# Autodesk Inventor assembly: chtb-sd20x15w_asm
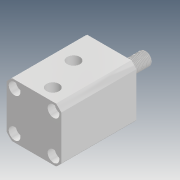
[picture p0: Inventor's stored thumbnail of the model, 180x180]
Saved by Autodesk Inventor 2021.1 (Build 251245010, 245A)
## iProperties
Company: Microsoft
Created: 2018-05
Part Number: chtb-sd20x15w_asm
Description: STEP AP214
Document SubType Name: Assembly
Designer: user
Title: chtb-sd20x15w_asm.STEP
Author: Windows
Revision Number: ÈÎºÎ
Sending System: SolidWorks 2015
Preprocessor: SwSTEP 2.0
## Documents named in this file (4)
- D:\Vault_2016\Projekty\Clamptek\Hydraulic\CHTB\CHTB-20\Inventor\CHTB-SD20x15W\chtb-sd20x15w_asm.iam
- D:\Vault_2016\Projekty\Clamptek\Hydraulic\CHTB\CHTB-20\Inventor\CHTB-SD20x15W\CHTB-SD20X15NBT.ipt
- D:\Vault_2016\Projekty\Clamptek\Hydraulic\CHTB\CHTB-20\Inventor\CHTB-SD20x15W\CHTB-SD20X15WHSG.ipt
- D:\Vault_2016\Projekty\Clamptek\Hydraulic\CHTB\CHTB-20\Inventor\CHTB-SD20x15W\QG.ipt
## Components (3 placed, 3 different names)
1. CHTB-SD20X15NBT_1
2. CHTB-SD20X15WHSG_2
3. QG_3
